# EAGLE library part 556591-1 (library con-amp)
AMP connector
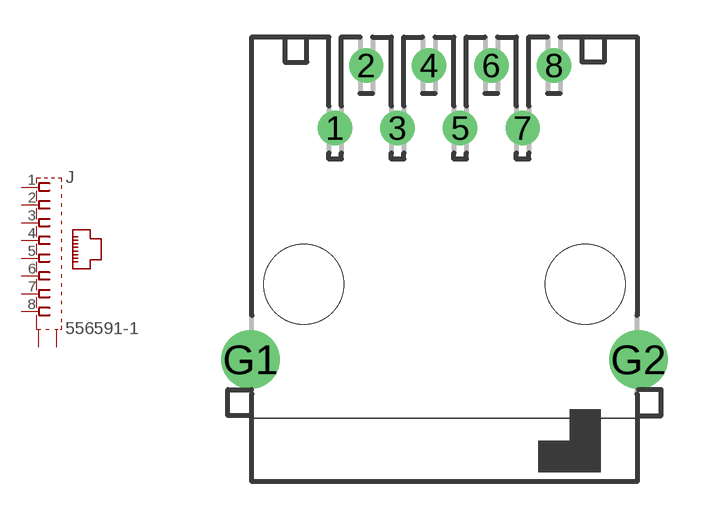
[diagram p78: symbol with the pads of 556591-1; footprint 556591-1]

Designator prefix J

## 556591-1 (MF: TYCO ELECTRONICS; MPN: 5556591-1; OC_FARNELL: 1771145; OC_NEWARK: 42K7303)  [556591-1]
1  1  pas
2  2  pas
3  3  pas
4  4  pas
5  5  pas
6  6  pas
7  7  pas
8  8  pas
G1  S1  pas
G2  S2  pas

## Footprint 556591-1 (pad centres in mm)
Modular Jack PC Board Ground
drill 0.889 round: 1 -4.445,6.35; 2 -3.175,8.89; 3 -1.905,6.35; 4 -0.635,8.89; 5 0.635,6.35; 6 1.905,8.89; 7 3.175,6.35; 8 4.445,8.89
drill 1.575 pad 2.184 round: G1 -7.874,-3.048; G2 7.874,-3.048
hole 3.251 at -5.715,0
hole 3.251 at 5.715,0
